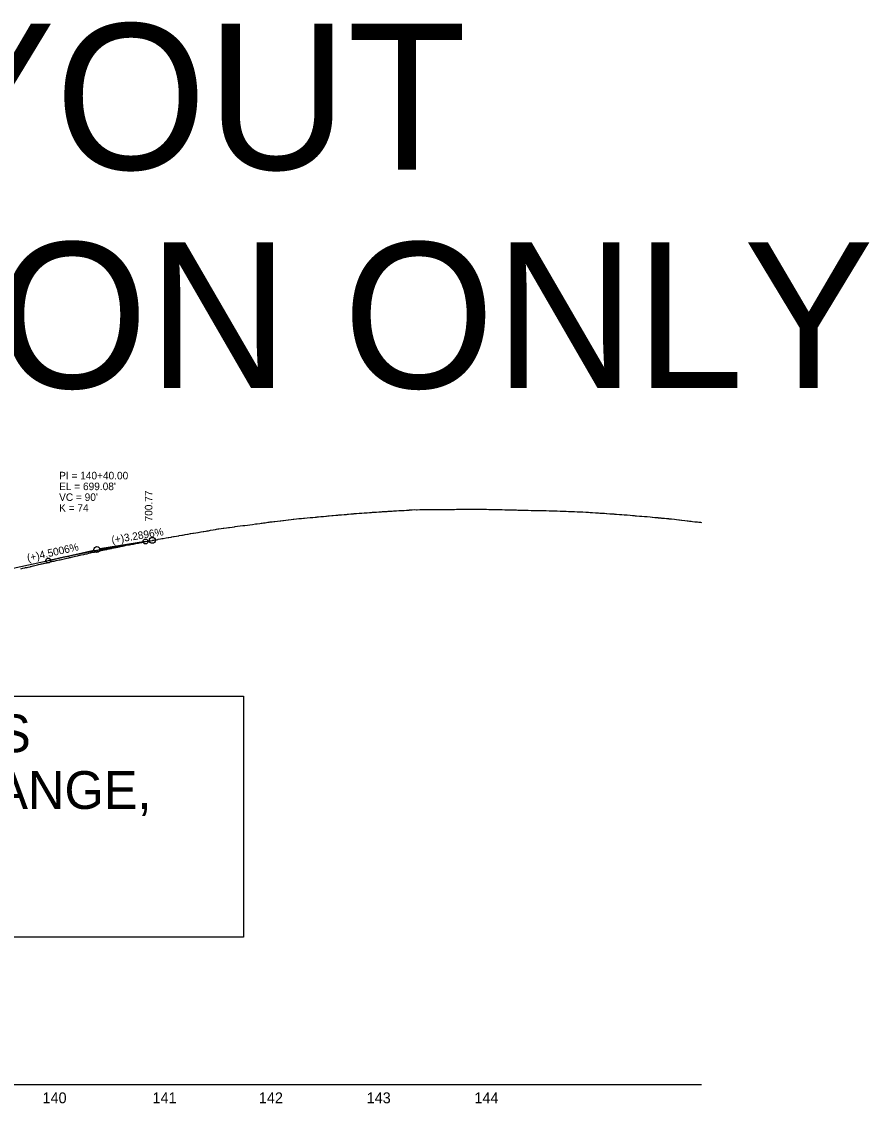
# Model space of a CAD drawing. Extents: x 1518255 to 1527303, y 471773 to 504546.
# Drawn here: x 1521041 to 1521826, y 497627 to 498629 of the extents above; entities that cross this region are included whole.
import ezdxf

# ---------------------------------------------------------------- set-up
doc = ezdxf.new("R2010")
doc.units = 0
for name, color, linetype in [('Default', 7, 'Continuous'), ('Exist Profile Cell', 7, 'Continuous'), ('Exist Vertical Profile Ground Line', 7, 'Continuous'), ('Exist Vertical Profile Horizontal Axis Label Major', 7, 'Continuous'), ('Prop Grid Mask', 7, 'Continuous'), ('Prop Vertical Profile Curve Label', 7, 'Continuous'), ('Prop Vertical Profile Grade Label', 7, 'Continuous'), ('Prop VPI Label', 7, 'Continuous')]:
    doc.layers.add(name, color=color, linetype=linetype)

msp = doc.modelspace()

# ---------------------------------------------------------------- linework, layer by layer
at = {"layer": 'Exist Profile Cell'}
msp.add_line((1519570.4, 497645), (1521670.4, 497645), dxfattribs=at)
at = {"layer": 'Exist Vertical Profile Ground Line'}
msp.add_lwpolyline([(1521040, 498122.6), (1521041.8, 498123), (1521043.5, 498123.4), (1521044.3, 498123.6), (1521045, 498123.8), (1521045.7, 498123.9), (1521046.6, 498124.1), (1521048.5, 498124.5), (1521049, 498124.6), (1521049.5, 498124.8), (1521051.2, 498125.2), (1521051.6, 498125.3), (1521052.9, 498125.6), (1521054.1, 498125.9), (1521055.4, 498126.2), (1521056.4, 498126.4), (1521058, 498126.7), (1521059.1, 498127), (1521059.7, 498127.2), (1521060.8, 498127.4), (1521061.7, 498127.7), (1521062.2, 498127.8), (1521062.6, 498127.9), (1521064.2, 498128.2), (1521064.8, 498128.4), (1521066.5, 498128.7), (1521067, 498128.9), (1521067.5, 498129), (1521068.7, 498129.2), (1521069.6, 498129.5), (1521070.2, 498129.6), (1521070.7, 498129.7), (1521072.8, 498130.2), (1521075.3, 498130.7), (1521076.5, 498131), (1521077.6, 498131.3), (1521080.2, 498131.8), (1521081.3, 498132.1), (1521082.8, 498132.4), (1521084.4, 498132.7), (1521085, 498132.9), (1521085.8, 498133.1), (1521088.2, 498133.6), (1521090.7, 498134.2), (1521092.3, 498134.5), (1521093.3, 498134.8), (1521095, 498135.2), (1521095.8, 498135.4), (1521098.3, 498135.9), (1521100.1, 498136.3), (1521100.6, 498136.4), (1521101.3, 498136.5), (1521102.9, 498136.9), (1521104.5, 498137.2), (1521105.5, 498137.5), (1521108.1, 498138), (1521110.3, 498138.5), (1521110.9, 498138.7), (1521112.5, 498139), (1521112.9, 498139.1), (1521113.3, 498139.2), (1521115.4, 498139.7), (1521115.9, 498139.8), (1521117.4, 498140.1), (1521119.6, 498140.5), (1521120.1, 498140.6), (1521121.7, 498141), (1521122.2, 498141.1), (1521122.6, 498141.2), (1521123.8, 498141.4), (1521124.6, 498141.6), (1521125.9, 498141.9), (1521126.5, 498142), (1521127.3, 498142.2), (1521128.1, 498142.4), (1521129.7, 498142.7), (1521131.2, 498143), (1521131.6, 498143.1), (1521132.1, 498143.2), (1521132.4, 498143.3), (1521134, 498143.6), (1521135.1, 498143.7), (1521135.5, 498143.8), (1521136.7, 498144.1), (1521137.5, 498144.3), (1521139.1, 498144.6), (1521139.5, 498144.7), (1521140.6, 498144.9), (1521141.8, 498145.1), (1521143.8, 498145.5), (1521144.4, 498145.5), (1521146.6, 498146), (1521147.4, 498146.2), (1521148.8, 498146.4), (1521149.2, 498146.5), (1521149.6, 498146.6), (1521149.9, 498146.7), (1521151.9, 498147), (1521153.4, 498147.3), (1521154.6, 498147.5), (1521155.3, 498147.7), (1521157, 498148), (1521158.8, 498148.3), (1521159.7, 498148.5), (1521161.8, 498148.9), (1521162.3, 498149), (1521163.1, 498149.1), (1521164.5, 498149.4), (1521164.9, 498149.5), (1521166.8, 498149.8), (1521167.2, 498149.9), (1521169.3, 498150.3), (1521170.4, 498150.5), (1521171, 498150.6), (1521171.5, 498150.6), (1521171.9, 498150.7), (1521174.4, 498151.2), (1521176.3, 498151.5), (1521177, 498151.6), (1521179.1, 498152), (1521179.7, 498152.1), (1521181.2, 498152.4), (1521181.7, 498152.5), (1521182.1, 498152.6), (1521184.1, 498152.9), (1521186.2, 498153.2), (1521186.7, 498153.3), (1521189.2, 498153.7), (1521189.6, 498153.8), (1521191.2, 498154.1), (1521192.3, 498154.3), (1521194.3, 498154.6), (1521195, 498154.7), (1521197, 498155.1), (1521197.5, 498155.1), (1521199.3, 498155.5), (1521199.6, 498155.5), (1521200, 498155.6), (1521202.1, 498155.9), (1521204, 498156.2), (1521204.3, 498156.3), (1521206.6, 498156.7), (1521206.9, 498156.7), (1521208.8, 498157), (1521209.4, 498157.1), (1521211.6, 498157.5), (1521212.6, 498157.6), (1521213, 498157.7), (1521213.8, 498157.8), (1521215.6, 498158.2), (1521218.1, 498158.6), (1521220.3, 498159), (1521221.1, 498159.2), (1521222.5, 498159.5), (1521222.9, 498159.6), (1521223.3, 498159.6), (1521225.4, 498159.9), (1521227.5, 498160.1), (1521228, 498160.1), (1521230.3, 498160.5), (1521230.6, 498160.5), (1521232.2, 498160.7), (1521233.1, 498160.9), (1521235.7, 498161.2), (1521238, 498161.5), (1521238.5, 498161.6), (1521240.5, 498161.9), (1521243, 498162.2), (1521245.6, 498162.6), (1521247.1, 498162.8), (1521247.4, 498162.8), (1521249.8, 498163.1), (1521252.1, 498163.4), (1521254.6, 498163.7), (1521257.2, 498164.1), (1521258.8, 498164.3), (1521261.2, 498164.6), (1521262.5, 498164.7), (1521263.6, 498164.9), (1521264.7, 498165), (1521266.3, 498165.2), (1521268.8, 498165.6), (1521270.1, 498165.8), (1521271, 498165.9), (1521272.6, 498166.1), (1521274.2, 498166.3), (1521275.2, 498166.5), (1521277.7, 498166.8), (1521280.3, 498167.1), (1521280.7, 498167.1), (1521282.5, 498167.4), (1521283.1, 498167.4), (1521285.3, 498167.7), (1521287.5, 498167.9), (1521287.9, 498168), (1521290.4, 498168.3), (1521292.1, 498168.4), (1521292.7, 498168.5), (1521295.2, 498168.8), (1521297.6, 498169), (1521298, 498169), (1521300, 498169.2), (1521301.9, 498169.4), (1521302.8, 498169.5), (1521305.2, 498169.7), (1521307.9, 498170), (1521310.4, 498170.2), (1521312.7, 498170.4), (1521313.8, 498170.5), (1521314.5, 498170.6), (1521315.4, 498170.7), (1521315.8, 498170.7), (1521317.8, 498170.9), (1521319.8, 498171.1), (1521320.4, 498171.1), (1521322.6, 498171.3), (1521323.1, 498171.4), (1521324.2, 498171.5), (1521325.3, 498171.6), (1521325.6, 498171.6), (1521328.1, 498171.8), (1521329.4, 498171.9), (1521331.6, 498172.1), (1521332, 498172.2), (1521333.5, 498172.3), (1521334.6, 498172.4), (1521337.1, 498172.6), (1521339.3, 498172.8), (1521339.9, 498172.9), (1521341.7, 498173), (1521342.6, 498173.1), (1521343.5, 498173.2), (1521345.6, 498173.4), (1521346.5, 498173.4), (1521346.9, 498173.4), (1521348.2, 498173.6), (1521348.8, 498173.7), (1521350.8, 498173.8), (1521353.3, 498174), (1521355.3, 498174.2), (1521355.9, 498174.2), (1521357.9, 498174.3), (1521358.3, 498174.4), (1521360.2, 498174.5), (1521360.8, 498174.5), (1521363, 498174.7), (1521364.5, 498174.8), (1521364.9, 498174.8), (1521365.6, 498174.9), (1521366.5, 498174.9), (1521366.9, 498175), (1521369.1, 498175.1), (1521369.4, 498175.1), (1521371.5, 498175.3), (1521372.9, 498175.4), (1521373.9, 498175.4), (1521375, 498175.5), (1521376.4, 498175.6), (1521376.7, 498175.6), (1521378.6, 498175.7), (1521379.3, 498175.7), (1521380.1, 498175.8), (1521382.3, 498175.9), (1521382.7, 498176), (1521383.9, 498176), (1521385, 498176.1), (1521385.3, 498176.1), (1521387.8, 498176.3), (1521390, 498176.4), (1521390.8, 498176.5), (1521392.1, 498176.6), (1521393.6, 498176.7), (1521394.9, 498176.7), (1521397.1, 498176.8), (1521397.6, 498176.9), (1521399.6, 498177), (1521400.1, 498177.1), (1521401.7, 498177.2), (1521402.1, 498177.3), (1521402.4, 498177.3), (1521404.5, 498177.5), (1521406.5, 498177.3), (1521407.1, 498177.3), (1521409.6, 498177.4), (1521410.8, 498177.4), (1521411.1, 498177.4), (1521411.4, 498177.4), (1521413.6, 498177.4), (1521415.1, 498177.4), (1521415.6, 498177.4), (1521416.1, 498177.4), (1521418.6, 498177.5), (1521420.3, 498177.5), (1521422.5, 498177.6), (1521423.5, 498177.6), (1521425.1, 498177.6), (1521427.6, 498177.6), (1521428.1, 498177.6), (1521430.7, 498177.5), (1521433.2, 498177.6), (1521434.9, 498177.6), (1521435.8, 498177.6), (1521436.5, 498177.6), (1521439.1, 498177.6), (1521441.4, 498177.6), (1521441.7, 498177.6), (1521443.6, 498177.7), (1521444.1, 498177.7), (1521446.4, 498177.7), (1521449, 498177.7), (1521450.3, 498177.7), (1521452.7, 498177.7), (1521455, 498177.8), (1521457.8, 498177.8), (1521460.3, 498177.8), (1521462.8, 498177.8), (1521465.2, 498177.7), (1521466.1, 498177.7), (1521467, 498177.7), (1521468.7, 498177.7), (1521471.2, 498177.7), (1521473.6, 498177.6), (1521474, 498177.6), (1521476.3, 498177.6), (1521478.7, 498177.5), (1521481.3, 498177.4), (1521483.5, 498177.4), (1521485.9, 498177.4), (1521488.4, 498177.3), (1521491, 498177.3), (1521493.4, 498177.2), (1521494, 498177.2), (1521494.5, 498177.2), (1521496.7, 498177.2), (1521499.1, 498177.1), (1521500.2, 498177), (1521502.8, 498176.9), (1521505.2, 498176.9), (1521506.2, 498176.8), (1521507.7, 498176.8), (1521508.9, 498176.8), (1521510, 498176.8), (1521512.6, 498176.7), (1521513.2, 498176.6), (1521515.4, 498176.6), (1521515.7, 498176.6), (1521516.7, 498176.5), (1521518.3, 498176.5), (1521521, 498176.5), (1521521.6, 498176.5), (1521524, 498176.4), (1521526.6, 498176.4), (1521529.3, 498176.3), (1521529.7, 498176.3), (1521531.9, 498176.2), (1521534.5, 498176.2), (1521536.8, 498176.1), (1521539.5, 498176), (1521541.4, 498176), (1521541.8, 498175.9), (1521544.4, 498175.8), (1521545, 498175.8), (1521547.4, 498175.7), (1521547.9, 498175.7), (1521550, 498175.6), (1521550.3, 498175.6), (1521552.9, 498175.5), (1521555.3, 498175.4), (1521558.3, 498175.3), (1521559.5, 498175.2), (1521560.7, 498175.2), (1521563.3, 498175), (1521565.7, 498174.9), (1521567.3, 498174.8), (1521567.7, 498174.8), (1521569.5, 498174.7), (1521572.2, 498174.5), (1521574.2, 498174.4), (1521574.6, 498174.4), (1521575.2, 498174.3), (1521576.3, 498174.2), (1521576.6, 498174.2), (1521577.8, 498174.2), (1521580.2, 498174), (1521580.6, 498174), (1521582.5, 498173.8), (1521582.8, 498173.8), (1521585.5, 498173.6), (1521586.8, 498173.5), (1521589.2, 498173.4), (1521589.8, 498173.3), (1521591.4, 498173.2), (1521591.8, 498173.2), (1521594.5, 498173), (1521596.6, 498172.8), (1521598.8, 498172.6), (1521599.1, 498172.6), (1521599.5, 498172.5), (1521600.9, 498172.4), (1521601.7, 498172.4), (1521604.3, 498172.2), (1521606.7, 498172), (1521608, 498171.8), (1521609, 498171.7), (1521609.5, 498171.6), (1521610.3, 498171.6), (1521613, 498171.4), (1521615.3, 498171.2), (1521617.6, 498171.1), (1521618, 498171), (1521620.2, 498170.9), (1521622.8, 498170.6), (1521624.7, 498170.5), (1521625.1, 498170.4), (1521627.2, 498170.2), (1521627.8, 498170.2), (1521629.9, 498170), (1521630.3, 498169.9), (1521630.6, 498169.9), (1521631.3, 498169.9), (1521632.9, 498169.7), (1521633.3, 498169.6), (1521635.5, 498169.4), (1521635.8, 498169.3), (1521636.3, 498169.3), (1521638.1, 498169.1), (1521639.8, 498169), (1521640.2, 498168.9), (1521640.7, 498168.9), (1521642.3, 498168.7), (1521642.8, 498168.7), (1521645.5, 498168.4), (1521647.3, 498168.2), (1521649.5, 498167.9), (1521650.1, 498167.9), (1521651.8, 498167.7), (1521652.4, 498167.6), (1521655, 498167.3), (1521657.1, 498167.1), (1521658.1, 498167), (1521659.5, 498166.8), (1521660.8, 498166.6), (1521662, 498166.5), (1521664.4, 498166.2), (1521666.7, 498165.9), (1521668.1, 498165.8), (1521668.7, 498165.7), (1521669.4, 498165.6), (1521670.4, 498165.5)], dxfattribs=at)
at = {"layer": 'Prop Grid Mask'}
for p, q in [((1521155.4, 498147.8), (1521161.8, 498148.9)), ((1521032.9, 498123), (1521065.4, 498130.3))]:
    msp.add_line(p, q, dxfattribs=at)
msp.add_lwpolyline([(1520134.3, 498004.6), (1521246.1, 498004.6), (1521246.1, 497781.3), (1520134.3, 497781.3)], close=True, dxfattribs=at)
msp.add_spline([(1521065.4, 498130.3), (1521067.2, 498130.7), (1521069, 498131.1), (1521070.8, 498131.5), (1521072.6, 498131.9), (1521074.4, 498132.3), (1521076.2, 498132.7), (1521078, 498133.1), (1521079.8, 498133.5), (1521081.6, 498133.9), (1521083.4, 498134.2), (1521085.2, 498134.6), (1521087, 498135), (1521088.8, 498135.4), (1521090.6, 498135.8), (1521092.4, 498136.1), (1521094.2, 498136.5), (1521096, 498136.9), (1521097.8, 498137.2), (1521099.6, 498137.6), (1521101.4, 498138), (1521103.2, 498138.3), (1521105, 498138.7), (1521106.8, 498139), (1521108.6, 498139.4), (1521110.4, 498139.7), (1521112.2, 498140.1), (1521114, 498140.4), (1521115.8, 498140.8), (1521117.6, 498141.1), (1521119.4, 498141.5), (1521121.2, 498141.8), (1521123, 498142.1), (1521124.8, 498142.5), (1521126.6, 498142.8), (1521128.4, 498143.1), (1521130.2, 498143.5), (1521132, 498143.8), (1521133.8, 498144.1), (1521135.6, 498144.4), (1521137.4, 498144.8), (1521139.2, 498145.1), (1521141, 498145.4), (1521142.8, 498145.7), (1521144.6, 498146), (1521146.4, 498146.3), (1521148.2, 498146.6), (1521150, 498146.9), (1521151.8, 498147.2), (1521153.6, 498147.5), (1521155.4, 498147.8)], degree=3, dxfattribs=at)
at = {"layer": 'Prop Vertical Profile Curve Label'}
for centre in [(1521155.4, 498147.8), (1521065.4, 498130.3)]:
    msp.add_circle(centre, 2.25, dxfattribs=at)
at = {"layer": 'Prop VPI Label'}
for p, q in [((1521155.4, 498147.8), (1521113.1, 498140.9)), ((1521065.4, 498130.3), (1521107.7, 498139.8))]:
    msp.add_line(p, q, dxfattribs=at)
for centre in [(1521161.8, 498148.9), (1521110.4, 498140.4)]:
    msp.add_circle(centre, 2.75, dxfattribs=at)

# ---------------------------------------------------------------- texts
at = {"layer": 'Default'}
for s, p in [('DO NOT LAYOUT', (1519978.3, 498492.4)), ('FOR INFORMATION ONLY', (1519593.4, 498289.9))]:
    msp.add_text(s, height=135, dxfattribs=at).set_placement(p)
at = {"layer": 'Exist Vertical Profile Horizontal Axis Label Major'}
for s, p in [('140', (1521060, 497627.5)), ('141', (1521161.9, 497627.5)), ('142', (1521260.4, 497627.5)), ('143', (1521360.3, 497627.5)), ('144', (1521460.1, 497627.5))]:
    msp.add_text(s, height=10, dxfattribs=at).set_placement(p)
at = {"layer": 'Prop Vertical Profile Curve Label'}
for s, p in [("VC = 90'", (1521075.4, 498185.4)), ('K = 74', (1521075.4, 498175.4))]:
    msp.add_text(s, height=7, dxfattribs=at).set_placement(p)
at = {"layer": 'Prop Vertical Profile Grade Label'}
for s, rotation, p in [('(+)3.2896%', 9.3404, (1521124.5, 498145.8)), ('(+)4.5006%', 12.682, (1521046.5, 498129.1))]:
    msp.add_text(s, height=7, rotation=rotation, dxfattribs=at).set_placement(p)
at = {"layer": 'Prop VPI Label'}
for s, height, p in [('PI = 140+40.00', 7, (1521075.4, 498205.4)), ("EL = 699.08'", 7, (1521075.4, 498195.4)), ('DO NOT INCLUDE IN GREYLOCK PLANS', 35, (1520149.3, 497952.6)), ('NOTE: I-5507 DESIGN SUBJECT TO CHANGE,', 35, (1520149.3, 497900.1))]:
    msp.add_text(s, height=height, dxfattribs=at).set_placement(p)
msp.add_text('700.77', height=7, rotation=90, dxfattribs=at).set_placement((1521161.8, 498166.4))

doc.saveas('drawing.dxf')
